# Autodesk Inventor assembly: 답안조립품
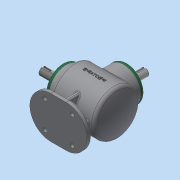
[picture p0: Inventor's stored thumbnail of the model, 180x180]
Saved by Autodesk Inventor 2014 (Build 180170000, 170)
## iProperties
Created: 2023-01
Part Number: 답안조립품
Document SubType Name: Assembly
Designer: dg
Author: dg
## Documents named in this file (14)
- C:\Users\dg\Desktop\730106V1014\답안조립품.iam
- C:\Users\dg\Desktop\730106V1014\본체.ipt
- C:\Users\dg\Desktop\730106V1014\M4.ipt
- C:\Users\dg\Desktop\730106V1014\메인 베벨기어.ipt
- C:\Users\dg\Desktop\730106V1014\메인 축.ipt
- 메인 축.ipt
- C:\Users\dg\Desktop\730106V1014\베어링 6203.ipt
- C:\Users\dg\Desktop\730106V1014\서브 베벨기어.ipt
- C:\Users\dg\Desktop\730106V1014\서브 축.ipt
- 서브 축.ipt
- C:\Users\dg\Desktop\730106V1014\오일실 17 32 8.ipt
- C:\Users\dg\Desktop\730106V1014\커버.ipt
- C:\Users\dg\Desktop\730106V1014\키 4x4.ipt
- C:\Users\dg\Desktop\730106V1014\키 5x5.ipt
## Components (8 placed, 1 different names)
1. M4:1
2. M4:3
3. M4:4
4. M4:5
5. M4:2
6. M4:6
7. M4:7
8. M4:8
